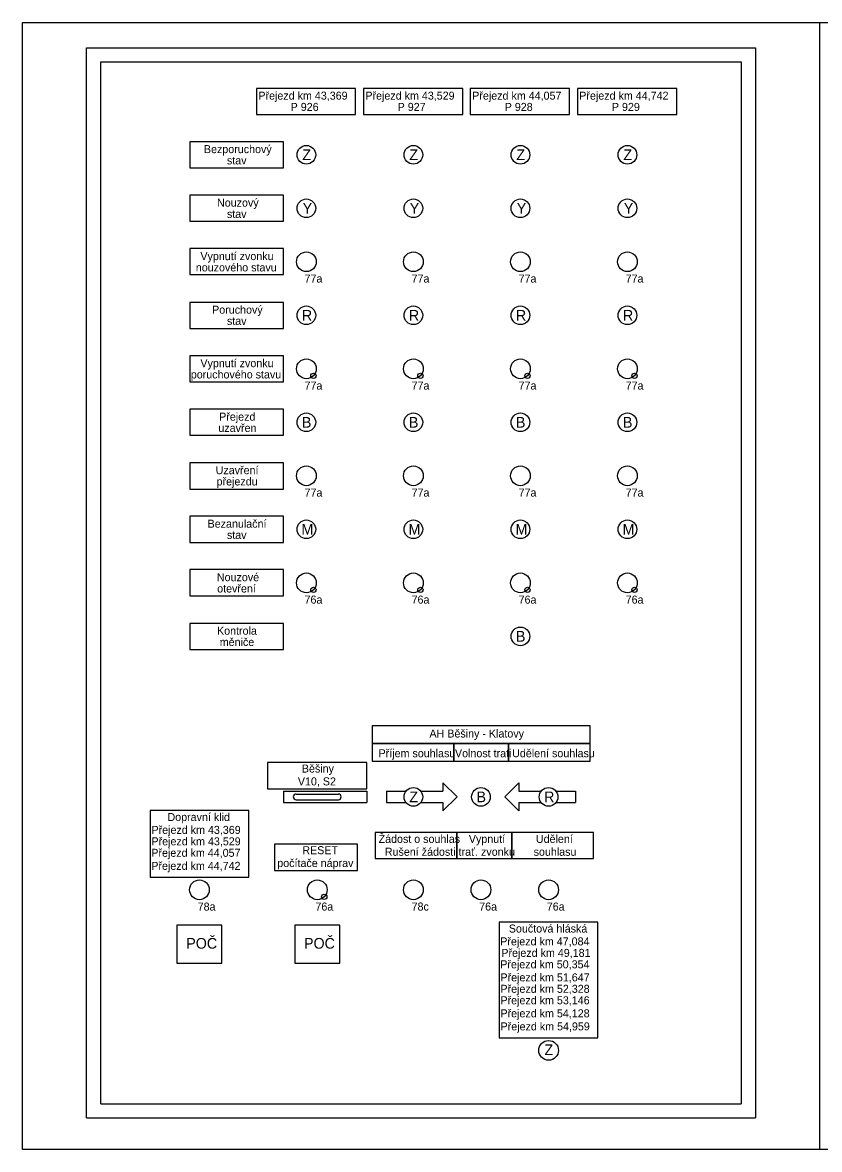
# Model space of a CAD drawing. Extents: x 210 to 2310, y -384 to 929.
# Drawn here: x 210 to 420, y -384.2 to -87.2 of the extents above; entities that cross this region are included whole.
import ezdxf

# ---------------------------------------------------------------- set-up
doc = ezdxf.new("R2010")
doc.units = 0
doc.layers.add('ostatní', color=7, linetype='Continuous')
doc.layers.add('rámeček', color=7, linetype='Continuous')

# ---------------------------------------------------------------- blocks, each defined once
blk = doc.blocks.new('uzel')
at = {"layer": 'ostatní'}
blk.add_circle((0, 0), 0.0625, dxfattribs=at)
blk.add_circle((0, 0), 0.0625, dxfattribs=at)
blk = doc.blocks.new('Sklo dlouhé')
for p, q in [((-15, 2), (15, 2)), ((-15, -2), (15, -2))]:
    blk.add_line(p, q)
for centre, start, end in [((-15, 0), 90, 270), ((15, 0), 270, 90)]:
    blk.add_arc(centre, 2, start, end)
blk = doc.blocks.new('Poč. nové')
blk.add_lwpolyline([(-16, -14), (16, -14), (16, 13), (-16, 13)], close=True)

msp = doc.modelspace()

# ---------------------------------------------------------------- linework, layer by layer
for p, q in [((226.89, -375.89), (226.89, -93.85)), ((226.89, -93.85), (403.11, -93.85)), ((403.11, -93.85), (403.11, -375.89)), ((230.61, -372.18), (230.61, -97.56)), ((230.61, -97.56), (399.39, -97.56)), ((399.39, -97.56), (399.39, -372.18)), ((320.78, -287.56), (324.5, -291.28)), ((320.78, -287.56), (320.78, -289.79)), ((337.11, -291.28), (340.82, -287.56)), ((340.82, -287.56), (340.82, -289.79)), ((278.75, -289.79), (278.75, -292.76)), ((278.75, -289.79), (300.7, -289.79)), ((300.7, -289.79), (300.7, -292.76)), ((305.94, -289.79), (311.14, -289.79)), ((305.94, -289.79), (305.94, -292.76)), ((314.85, -289.79), (320.78, -289.79)), ((340.82, -289.79), (346.76, -289.79)), ((350.47, -289.79), (355.67, -289.79)), ((355.67, -289.79), (355.67, -292.76)), ((278.75, -292.76), (300.7, -292.76)), ((305.94, -292.76), (311.14, -292.76)), ((314.85, -292.76), (320.78, -292.76)), ((320.78, -294.99), (324.5, -291.28)), ((320.78, -292.76), (320.78, -294.99)), ((337.11, -291.28), (340.82, -294.99)), ((340.82, -292.76), (340.82, -294.99)), ((340.82, -292.76), (346.76, -292.76)), ((350.47, -292.76), (355.67, -292.76)), ((230.61, -372.18), (399.39, -372.18)), ((226.89, -375.89), (403.11, -375.89))]:
    msp.add_line(p, q)
for points in [[(271.62, -111.46), (297.77, -111.46), (297.77, -104.57), (271.62, -104.57)], [(299.88, -111.46), (326.03, -111.46), (326.03, -104.57), (299.88, -104.57)], [(327.99, -111.46), (354.14, -111.46), (354.14, -104.57), (327.99, -104.57)], [(356.25, -111.46), (382.39, -111.46), (382.39, -104.57), (356.25, -104.57)], [(254.05, -125.52), (278.79, -125.52), (278.79, -118.63), (254.05, -118.63)], [(254.05, -139.58), (278.79, -139.58), (278.79, -132.69), (254.05, -132.69)], [(254.05, -153.63), (278.79, -153.63), (278.79, -146.75), (254.05, -146.75)], [(254.05, -167.83), (278.79, -167.83), (278.79, -160.94), (254.05, -160.94)], [(254.05, -181.89), (278.79, -181.89), (278.79, -175), (254.05, -175)], [(254.05, -195.95), (278.79, -195.95), (278.79, -189.06), (254.05, -189.06)], [(254.05, -210.14), (278.79, -210.14), (278.79, -203.26), (254.05, -203.26)], [(254.05, -224.2), (278.79, -224.2), (278.79, -217.31), (254.05, -217.31)], [(254.05, -238.26), (278.79, -238.26), (278.79, -231.37), (254.05, -231.37)], [(254.05, -252.46), (278.79, -252.46), (278.79, -245.57), (254.05, -245.57)], [(302.11, -277.2), (359.6, -277.2), (359.6, -272.56), (302.11, -272.56)], [(302.11, -281.84), (323.61, -281.84), (323.61, -277.2), (302.11, -277.2)], [(323.61, -281.84), (338.09, -281.84), (338.09, -277.2), (323.61, -277.2)], [(338.09, -281.84), (359.6, -281.84), (359.6, -277.2), (338.09, -277.2)], [(274.55, -289.15), (300.7, -289.15), (300.7, -282.26), (274.55, -282.26)], [(243.6, -312.48), (269.61, -312.48), (269.61, -294.91), (243.6, -294.91)], [(302.95, -307.56), (324.46, -307.56), (324.46, -300.67), (302.95, -300.67)], [(324.46, -307.56), (338.94, -307.56), (338.94, -300.67), (324.46, -300.67)], [(338.94, -307.56), (360.44, -307.56), (360.44, -300.67), (338.94, -300.67)], [(276.38, -310.65), (298.31, -310.65), (298.31, -303.77), (276.38, -303.77)], [(335.6, -354.79), (361.6, -354.79), (361.6, -324.29), (335.6, -324.29)]]:
    msp.add_lwpolyline(points, close=True)
for centre, radius in [((284.79, -122.05), 2.46), ((312.99, -122.05), 2.46), ((341.2, -122.05), 2.46), ((369.4, -122.05), 2.46), ((284.79, -136.15), 2.46), ((312.99, -136.15), 2.46), ((341.2, -136.15), 2.46), ((369.4, -136.15), 2.46), ((284.79, -150.25), 2.6), ((312.99, -150.25), 2.6), ((341.2, -150.25), 2.6), ((369.4, -150.25), 2.6), ((284.79, -164.36), 2.46), ((312.99, -164.36), 2.46), ((341.2, -164.36), 2.46), ((369.4, -164.36), 2.46), ((284.79, -178.46), 2.6), ((312.99, -178.46), 2.6), ((341.2, -178.46), 2.6), ((369.4, -178.46), 2.6), ((284.79, -192.56), 2.46), ((312.99, -192.56), 2.46), ((341.2, -192.56), 2.46), ((369.4, -192.56), 2.46), ((284.79, -206.66), 2.6), ((312.99, -206.66), 2.6), ((341.2, -206.66), 2.6), ((369.4, -206.66), 2.6), ((284.79, -220.76), 2.46), ((312.99, -220.76), 2.46), ((341.2, -220.76), 2.46), ((369.4, -220.76), 2.46), ((284.79, -234.87), 2.6), ((312.99, -234.87), 2.6), ((341.2, -234.87), 2.6), ((369.4, -234.87), 2.6), ((341.2, -248.97), 2.46), ((312.99, -291.28), 2.46), ((330.8, -291.28), 2.46), ((348.62, -291.28), 2.46), ((256.62, -315.77), 2.6), ((287.66, -315.77), 2.6), ((312.99, -315.77), 2.6), ((330.8, -315.77), 2.6), ((348.62, -315.77), 2.6), ((348.62, -358.08), 2.6)]:
    msp.add_circle(centre, radius)
at = {"layer": 'rámeček'}
for points in [[(210, -87.2), (630, -87.2), (630, -384.2), (210, -384.2)], [(210, -87.2), (420, -87.2), (420, -384.2), (210, -384.2)]]:
    msp.add_lwpolyline(points, close=True, dxfattribs=at)

# ---------------------------------------------------------------- block references
for name, p, xscale, yscale in [('uzel', (286.64, -180.31), 11.13328925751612, 11.13328925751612), ('uzel', (314.85, -180.31), 11.13328925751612, 11.13328925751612), ('uzel', (343.05, -180.31), 11.13328925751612, 11.13328925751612), ('uzel', (371.26, -180.31), 11.13328925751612, 11.13328925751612), ('uzel', (286.64, -236.72), 11.13328925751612, 11.13328925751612), ('uzel', (314.85, -236.72), 11.13328925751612, 11.13328925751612), ('uzel', (343.05, -236.72), 11.13328925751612, 11.13328925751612), ('uzel', (371.26, -236.72), 11.13328925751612, 11.13328925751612), ('Sklo dlouhé', (287.66, -291.28), 0.371109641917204, 0.3711096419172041), ('uzel', (289.51, -317.62), 11.13328925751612, 11.13328925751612), ('Poč. nové', (256.62, -329.87), 0.371109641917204, 0.3711096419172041), ('Poč. nové', (287.66, -329.87), 0.371109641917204, 0.3711096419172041)]:
    msp.add_blockref(name, p, dxfattribs=dict(xscale=xscale, yscale=yscale))

# ---------------------------------------------------------------- texts
for s, height, p in [('Přejezd km 43,369', 2.1086, (272.14, -107.52)), ('Přejezd km 43,529', 2.1086, (300.34, -107.52)), ('Přejezd km 44,057', 2.1086, (328.5, -107.52)), ('Přejezd km 44,742', 2.1086, (356.71, -107.52)), ('P 926', 2.109, (280.65, -110.49)), ('P 927', 2.109, (308.85, -110.49)), ('P 928', 2.109, (337.06, -110.49)), ('P 929', 2.109, (365.3, -110.49)), ('Bezporuchový', 2.1086, (257.79, -121.62)), ('Z', 2.81, (283.72, -123.46)), ('Z', 2.81, (311.92, -123.46)), ('Z', 2.81, (340.12, -123.46)), ('Z', 2.81, (368.33, -123.46)), ('stav', 2.109, (263.86, -124.59)), ('Nouzový', 2.109, (261.25, -135.72)), ('Y', 2.81, (283.82, -137.56)), ('Y', 2.81, (312.03, -137.56)), ('Y', 2.81, (340.23, -137.56)), ('Y', 2.81, (368.44, -137.56)), ('stav', 2.109, (263.86, -138.69)), ('Vypnutí zvonku', 2.1086, (256.87, -149.82)), ('nouzového stavu', 2.1086, (255.66, -152.79)), ('77a', 2.109, (284.31, -155.72)), ('77a', 2.109, (312.52, -155.72)), ('77a', 2.109, (340.72, -155.72)), ('77a', 2.109, (368.93, -155.72)), ('Poruchový', 2.109, (259.96, -163.93)), ('R', 2.81, (283.61, -165.76)), ('R', 2.81, (311.81, -165.76)), ('R', 2.81, (340.02, -165.76)), ('R', 2.81, (368.22, -165.76)), ('stav', 2.109, (263.86, -166.89)), ('Vypnutí zvonku', 2.1086, (256.87, -178.03)), ('poruchového stavu', 2.1086, (254.34, -181)), ('77a', 2.109, (284.31, -183.93)), ('77a', 2.109, (312.52, -183.93)), ('77a', 2.109, (340.72, -183.93)), ('77a', 2.109, (368.93, -183.93)), ('Přejezd', 2.109, (261.81, -192.13)), ('uzavřen', 2.109, (261.61, -195.1)), ('B', 2.81, (283.61, -193.97)), ('B', 2.81, (311.81, -193.97)), ('B', 2.81, (340.02, -193.97)), ('B', 2.81, (368.22, -193.97)), ('Uzavření', 2.109, (260.89, -206.23)), ('přejezdu', 2.109, (261.13, -209.2)), ('77a', 2.109, (284.31, -212.13)), ('77a', 2.109, (312.52, -212.13)), ('77a', 2.109, (340.72, -212.13)), ('77a', 2.109, (368.93, -212.13)), ('Bezanulační', 2.1086, (258.76, -220.33)), ('M', 2.81, (283.5, -222.17)), ('M', 2.81, (311.71, -222.17)), ('M', 2.81, (339.91, -222.17)), ('M', 2.81, (368.12, -222.17)), ('stav', 2.109, (263.86, -223.3)), ('Nouzové', 2.109, (261.21, -234.44)), ('otevření', 2.109, (261.29, -237.41)), ('76a', 2.109, (284.31, -240.34)), ('76a', 2.109, (312.52, -240.34)), ('76a', 2.109, (340.72, -240.34)), ('76a', 2.109, (368.93, -240.34)), ('Kontrola', 2.109, (261.25, -248.54)), ('měniče', 2.109, (261.97, -251.51)), ('B', 2.81, (340.02, -250.37)), ('AH Běšiny - Klatovy', 2.1086, (317.23, -275.63)), ('Příjem souhlasu', 2.1086, (303.82, -280.83)), ('Volnost trati', 2.1086, (323.95, -280.83)), ('Udělení souhlasu', 2.1086, (339.02, -280.83)), ('Běšiny', 2.109, (283.6, -284.86)), ('V10, S2', 2.109, (282.55, -288.25)), ('Z', 2.81, (311.92, -292.68)), ('B', 2.81, (329.63, -292.68)), ('R', 2.81, (347.44, -292.68)), ('Dopravní klid', 2.1086, (248.19, -297.64)), ('Přejezd km 43,369', 2.1086, (243.97, -301.03)), ('Přejezd km 43,529', 2.1086, (243.97, -304.05)), ('Žádost o souhlas', 2.1086, (303.82, -303.41)), ('Vypnutí', 2.109, (327.61, -303.41)), ('Udělení', 2.109, (345.28, -303.41)), ('Přejezd km 44,057', 2.1086, (243.93, -307.07)), ('RESET', 2.109, (283.72, -306.38)), ('Rušení žádosti', 2.1086, (305.47, -306.8)), ('trať. zvonku', 2.1086, (324.9, -306.8)), ('souhlasu', 2.109, (344.68, -306.8)), ('Přejezd km 44,742', 2.1086, (243.93, -310.51)), ('počítače náprav', 2.1086, (277.13, -309.77)), ('78a', 2.109, (256.15, -321.24)), ('76a', 2.109, (287.18, -321.24)), ('78c', 2.109, (312.52, -321.24)), ('76a', 2.109, (330.33, -321.24)), ('76a', 2.109, (348.14, -321.24)), ('Součtová hláská', 2.1086, (338.14, -327.03)), ('POČ', 2.811, (253.14, -331.28)), ('POČ', 2.811, (284.17, -331.28)), ('Přejezd km 47,084', 2.1086, (335.89, -330.42)), ('Přejezd km 49,181', 2.1086, (336.17, -333.44)), ('Přejezd km 50,354', 2.1086, (335.89, -336.46)), ('Přejezd km 51,647', 2.1086, (335.93, -339.9)), ('Přejezd km 52,328', 2.1086, (335.93, -342.92)), ('Přejezd km 53,146', 2.1086, (335.93, -345.94)), ('Přejezd km 54,128', 2.1086, (335.93, -349.38)), ('Přejezd km 54,959', 2.1086, (335.97, -352.82)), ('Z', 2.81, (347.55, -359.34))]:
    msp.add_text(s, height=height).set_placement(p)

doc.saveas('drawing.dxf')
